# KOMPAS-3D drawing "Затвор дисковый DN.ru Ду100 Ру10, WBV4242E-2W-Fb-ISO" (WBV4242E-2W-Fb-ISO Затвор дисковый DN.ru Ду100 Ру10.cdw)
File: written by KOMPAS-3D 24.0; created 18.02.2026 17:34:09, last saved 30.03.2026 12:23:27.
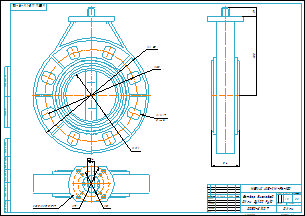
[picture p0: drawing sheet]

Document properties: Автор: R2D2; Форматы листов документа: A2; Полное имя файла: WBV4242E-2W-Fb-ISO Затвор дисковый DN.ru Ду100 Ру10.m3d; Масса: 2.02; Наименование: Затвор дисковый DN.ru Ду100 Ру10; Количество листов документа: 1; Примечание: D050-81207

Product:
- Part/product: Затвор дисковый DN.ru Ду100 Ру10  | designation WBV4242E-2W-Fb-ISO
    Масса: 2.02
    Раздел спецификации: Прочие изделия
    Форматы листов документа: A2
    Примечание: D050-81207

Views: Вид 1, Спереди, Проекционный вид 2, Проекционный вид 3
Referenced files in E:\Работа\Зайцев\WBV4242E-2W-Fb-ISO Затвор дисковый DN.ru Ду50-200 Ру10\DN100\: WBV4242E-2W-Fb-ISO Затвор дисковый DN.ru Ду100 Ру10.m3d
Referenced files in E:\Работа\Зайцев\Для компаса\: чертеж DN.ru А3.cdt
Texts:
  WBV4242E-2W-Fb-ISO
  ISO 5211 F05/F07
  чертеж DN.ru А3.cdt
  Затвор дисковый
  DN.ru Ду100 Ру10
  Затвор дисковый DN.ru Ду100 Ру10
  WBV4242E-2W-Fb-ISO Затвор дисковый DN.ru Ду100 Ру10
Dimensions and other numbers on the sheet: 0; 3; 2; 4; 226,5; 100; 181; 8 отв.; 17; 155; 54; 8; 14; 70; 50; 1:1; 1; 2,02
